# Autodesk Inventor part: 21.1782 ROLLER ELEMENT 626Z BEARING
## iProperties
Created: 2007-05
Part Number: 21.1782 ROLLER ELEMENT 626Z BEARING
Material: Steel
Document SubType Name: Modeling
Designer: Andy Moles
Density: 7.85 g/cm^3
Author: Andy Moles
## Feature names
1. Extrusion1
2. Extrusion2
3. Mirror1
4. Fillet1
